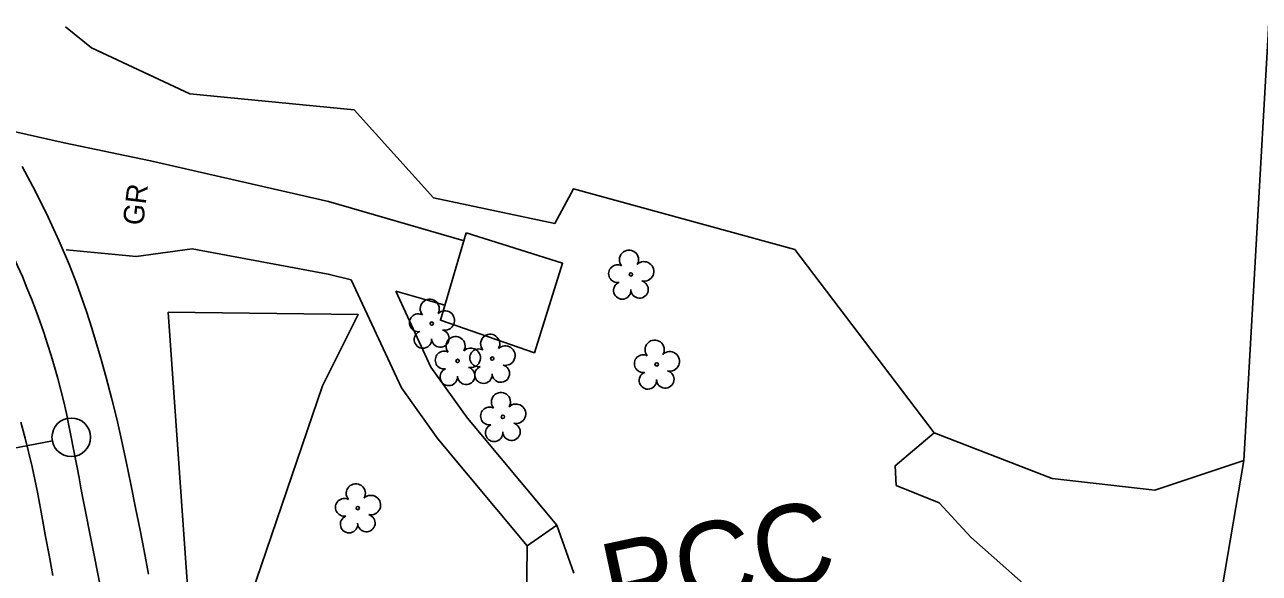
# Model space of a CAD drawing. Extents: x 479429 to 482809, y 488118 to 492379.
# Drawn here: x 481121.6 to 481361.5, y 491036.5 to 491143.2 of the extents above; entities that cross this region are included whole.
import ezdxf

# ---------------------------------------------------------------- set-up
doc = ezdxf.new("R2010")
doc.units = 0
for name, color, linetype in [('Exist Building Metal Canopy', 7, 'Continuous'), ('Exist Horizontal Alignment', 7, 'Continuous'), ('Exist Roads EOP', 7, 'Continuous'), ('Exist Roads EOP Other', 7, 'Continuous'), ('Exist Roads Soil', 7, 'Continuous'), ('Exist Roads Soil Text', 7, 'Continuous'), ('Exist Vegetation Hedge Row', 7, 'Continuous'), ('Exist Vegetation Tree CELL', 7, 'Continuous'), ('Exist Vegetation Woods Line', 7, 'Continuous')]:
    doc.layers.add(name, color=color, linetype=linetype)

msp = doc.modelspace()

# ---------------------------------------------------------------- linework, layer by layer
at = {"layer": 'Exist Building Metal Canopy'}
msp.add_lwpolyline([(481207.38, 491102.68), (481226.08, 491096.8), (481220.6, 491079.38), (481202.35, 491085.7), (481207.38, 491102.68)], dxfattribs=at)
at = {"layer": 'Exist Horizontal Alignment'}
msp.add_line((481126.93, 491062.26), (481008.98, 491039.95), dxfattribs=at)
msp.add_circle((481130.61, 491062.96), 3.75, dxfattribs=at)
for centre, radius, start, end in [((480982.98, 491035.04), 150.25, 10.7112, 39.2065), ((483795.69, 491567.07), 2712.34, 190.71117, 192.06493)]:
    msp.add_arc(centre, radius, start, end, dxfattribs=at)
at = {"layer": 'Exist Roads EOP'}
for points in [[(481121.04, 491115.59), (481123.64, 491110.73), (481126.11, 491105.78), (481128.27, 491101.07), (481130.27, 491096.42), (481131.65, 491092.9), (481133.58, 491087.42), (481134.62, 491084.2), (481136.3, 491078.53), (481137.37, 491074.6), (481138.41, 491070.61), (481139.44, 491066.56), (481140.39, 491062.45), (481141.26, 491058.26), (481142.17, 491053.84), (481143.11, 491049.24), (481143.97, 491044.92), (481144.75, 491040.86), (481145.59, 491036.37)], [(481127.05, 491036.1), (481126.28, 491040.02), (481125.6, 491043.66), (481125.01, 491046.98), (481124.06, 491052.27), (481123.01, 491057.2), (481121.63, 491062.76), (481120.8, 491065.9)]]:
    msp.add_lwpolyline(points, dxfattribs=at)
at = {"layer": 'Exist Roads EOP Other'}
msp.add_line((481219.21, 491041.83), (481224.96, 491045.86), dxfattribs=at)
for points in [[(481224.96, 491045.86), (481228.26, 491036.52)], [(481209.35, 491015.06), (481216.77, 491018.91), (481219.04, 491023.93), (481219.21, 491041.83)]]:
    msp.add_lwpolyline(points, dxfattribs=at)
at = {"layer": 'Exist Roads Soil'}
for points in [[(481116.84, 491122.97), (481129.2, 491120.2), (481146.03, 491116.72), (481180.59, 491108.8), (481206.93, 491101.17)], [(481185.01, 491093.54), (481180.55, 491094.68), (481154.12, 491099.59), (481143.19, 491098.13), (481129.64, 491099.4)], [(481219.21, 491041.83), (481201.86, 491062.65), (481194.75, 491072.58), (481185.01, 491093.54)], [(481224.96, 491045.86), (481207.62, 491066.69), (481200.51, 491076.62), (481193.66, 491091.35)], [(481203.22, 491088.64), (481193.66, 491091.35)]]:
    msp.add_lwpolyline(points, dxfattribs=at)
at = {"layer": 'Exist Vegetation Hedge Row'}
msp.add_line((481358.47, 491058.43), (481349.63, 491006.82), dxfattribs=at)
msp.add_lwpolyline([(481309.55, 490998.59), (481317.17, 491013.08), (481316.79, 491033.53), (481305.4, 491043.54), (481299.28, 491050.19), (481290.94, 491053.61), (481290.73, 491057.43), (481298.3, 491063.81)], dxfattribs=at)
at = {"layer": 'Exist Vegetation Tree CELL'}
for p, q in [((481239.37, 491094.62), (481239.37, 491094.62)), ((481200.65, 491085.07), (481200.65, 491085.07)), ((481205.67, 491077.81), (481205.67, 491077.81)), ((481212.41, 491078.25), (481212.41, 491078.25)), ((481244.37, 491077.13), (481244.37, 491077.13)), ((481214.48, 491066.94), (481214.48, 491066.94)), ((481186.28, 491049.19), (481186.28, 491049.19))]:
    msp.add_line(p, q, dxfattribs=at)
for centre in [(481239.37, 491094.62), (481200.65, 491085.07), (481205.67, 491077.81), (481212.41, 491078.25), (481244.37, 491077.13), (481214.48, 491066.94), (481186.28, 491049.19)]:
    msp.add_circle(centre, 0.326, dxfattribs=at)
for centre, radius, start, end in [((481238.99, 491097.49), 1.86, 330.1651, 219.7134), ((481236.77, 491094.77), 1.73, 62.6636, 279.3457), ((481241.92, 491095.21), 1.9, 257.1011, 134.1999), ((481237.67, 491091.5), 1.69, 111.5671, 6.231), ((481241.04, 491091.72), 1.7, 181.2822, 74.56), ((481200.27, 491087.94), 1.86, 330.1651, 219.7134), ((481198.05, 491085.22), 1.73, 62.6636, 279.3457), ((481203.2, 491085.66), 1.9, 257.1011, 134.1999), ((481198.95, 491081.95), 1.69, 111.5671, 6.231), ((481202.33, 491082.17), 1.7, 181.2822, 74.56), ((481205.29, 491080.69), 1.86, 330.1651, 219.7134), ((481212.02, 491081.13), 1.86, 330.1651, 219.7134), ((481243.98, 491080), 1.86, 330.1651, 219.7134), ((481203.07, 491077.97), 1.73, 62.6636, 279.3457), ((481208.22, 491078.4), 1.9, 257.1011, 134.1999), ((481209.8, 491078.41), 1.73, 62.6636, 279.3457), ((481214.96, 491078.84), 1.9, 257.1011, 134.1999), ((481246.92, 491077.72), 1.9, 257.1011, 134.1999), ((481214.08, 491075.35), 1.7, 181.2822, 74.56), ((481241.76, 491077.28), 1.73, 62.6636, 279.3457), ((481203.97, 491074.69), 1.69, 111.5671, 6.231), ((481207.35, 491074.91), 1.7, 181.2822, 74.56), ((481210.71, 491075.13), 1.69, 111.5671, 6.231), ((481242.66, 491074.01), 1.69, 111.5671, 6.231), ((481246.04, 491074.23), 1.7, 181.2822, 74.56), ((481214.1, 491069.82), 1.86, 330.1651, 219.7134), ((481211.88, 491067.1), 1.73, 62.6636, 279.3457), ((481217.03, 491067.53), 1.9, 257.1011, 134.1999), ((481212.78, 491063.82), 1.69, 111.5671, 6.231), ((481216.16, 491064.04), 1.7, 181.2822, 74.56), ((481185.9, 491052.07), 1.86, 330.1651, 219.7134), ((481183.68, 491049.35), 1.73, 62.6636, 279.3457), ((481188.83, 491049.78), 1.9, 257.1011, 134.1999), ((481184.58, 491046.07), 1.69, 111.5671, 6.231), ((481187.96, 491046.29), 1.7, 181.2822, 74.56)]:
    msp.add_arc(centre, radius, start, end, dxfattribs=at)
at = {"layer": 'Exist Vegetation Woods Line'}
for points in [[(481345.68, 491317.77), (481353.11, 491285.94), (481369.31, 491248.07), (481358.47, 491058.43), (481341.15, 491052.66), (481321.21, 491054.95), (481298.3, 491063.81), (481271.21, 491099.5), (481228.18, 491111.26), (481224.55, 491104.53), (481200.99, 491109.54), (481185.6, 491126.62), (481153.65, 491129.73), (481134.53, 491138.7), (481129.51, 491142.77)], [(481149.44, 491087.31), (481186.39, 491086.83), (481179.45, 491072.97), (481162.56, 491023.49), (481153.86, 491024.79), (481149.44, 491087.31)]]:
    msp.add_lwpolyline(points, dxfattribs=at)

# ---------------------------------------------------------------- texts
at = {"layer": 'Exist Horizontal Alignment'}
msp.add_text('PCC', height=16, rotation=12.0649, dxfattribs=at).set_placement((481235.76, 491026.15))
at = {"layer": 'Exist Roads Soil Text'}
msp.add_text('GR', height=4, rotation=83.0725, dxfattribs=at).set_placement((481144.56, 491104.01))

doc.saveas('drawing.dxf')
